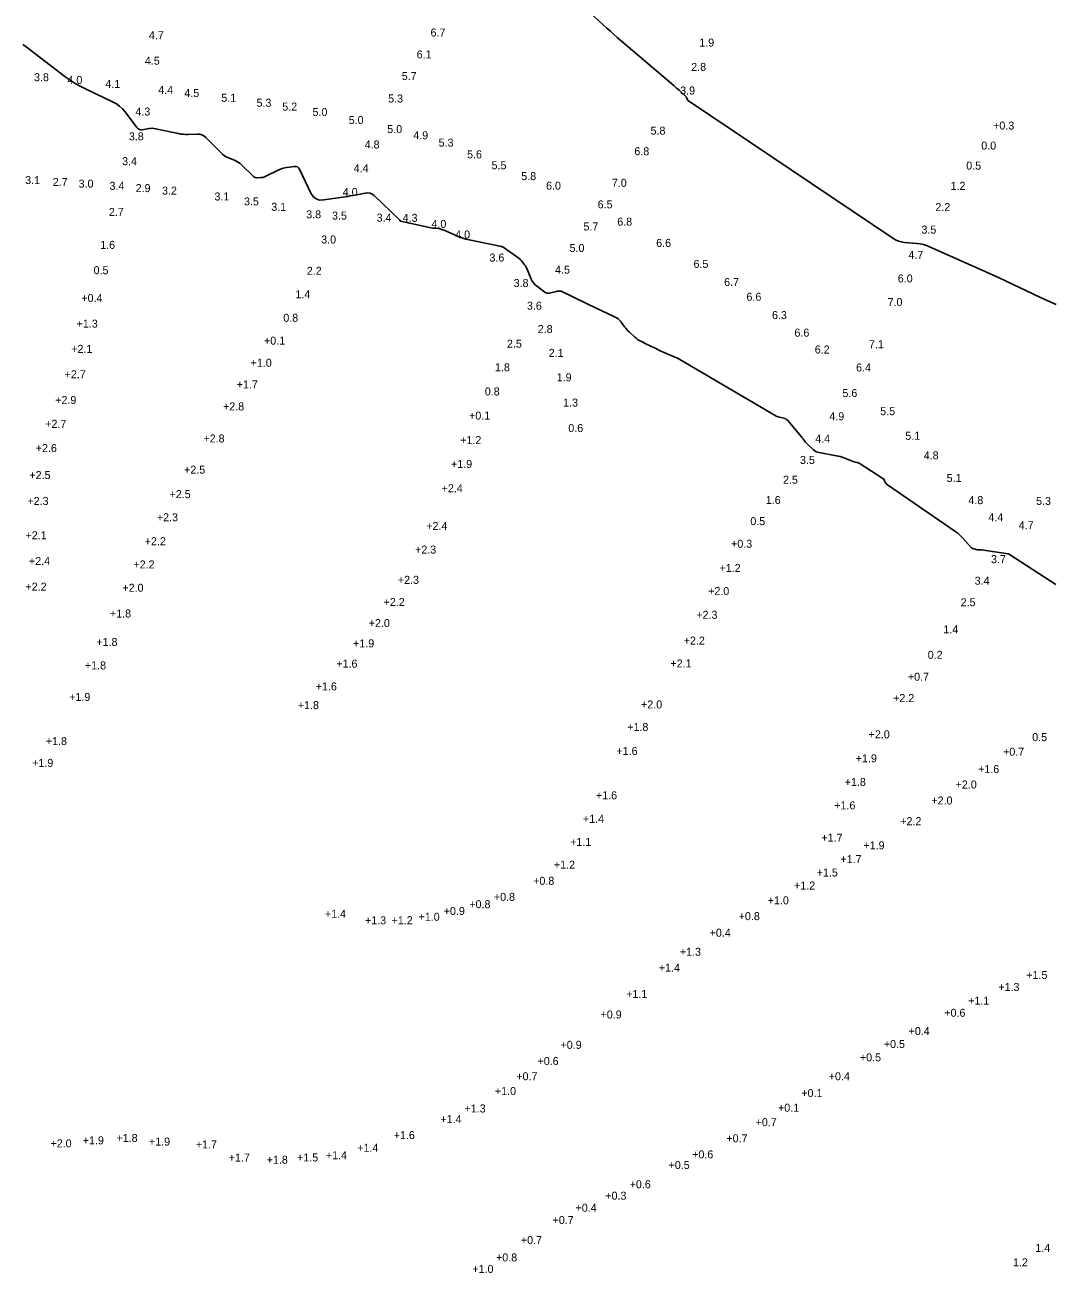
# Model space of a CAD drawing. Extents: x 837127 to 848654, y 3074248 to 3079868.
# Drawn here: x 845153 to 845553.7, y 3078633 to 3079120.3 of the extents above; entities that cross this region are included whole.
import ezdxf

# ---------------------------------------------------------------- set-up
doc = ezdxf.new("R2010")
doc.units = 0
for name, color, linetype in [('V-HYDS-MAJR', 7, 'Continuous'), ('V-HYDS-SOUN', 7, 'Continuous'), ('V-HYDS-SOUN-EXSS', 7, 'Continuous')]:
    doc.layers.add(name, color=color, linetype=linetype)

msp = doc.modelspace()

# ---------------------------------------------------------------- linework, layer by layer
at = {"layer": 'V-HYDS-MAJR'}
for points in [[(845373.58, 3079125.23), (845378.97, 3079120.24), (845380.29, 3079119.03), (845381.62, 3079117.83), (845382.97, 3079116.65), (845384.32, 3079115.48), (845406.55, 3079096.49), (845407.03, 3079096.08), (845407.5, 3079095.67), (845407.96, 3079095.26), (845408.43, 3079094.84), (845410.85, 3079092.66), (845411.02, 3079092.49), (845411.17, 3079092.31), (845411.3, 3079092.11), (845411.41, 3079091.89), (845411.98, 3079090.65), (845412, 3079090.61), (845412.04, 3079090.58), (845412.08, 3079090.55), (845412.12, 3079090.54), (845412.33, 3079090.51), (845412.38, 3079090.49), (845412.43, 3079090.48), (845412.48, 3079090.46), (845412.52, 3079090.43), (845491.95, 3079037.05), (845493.01, 3079036.42), (845494.12, 3079035.95), (845495.28, 3079035.62), (845496.49, 3079035.43), (845501.45, 3079034.97), (845502.67, 3079034.8), (845503.87, 3079034.54), (845505.05, 3079034.18), (845506.2, 3079033.73), (845523.53, 3079026.06), (845526.78, 3079024.61), (845530.01, 3079023.15), (845533.24, 3079021.66), (845536.45, 3079020.16), (845549.3, 3079014.1), (845552.52, 3079012.6), (845555.76, 3079011.15)], [(845555.56, 3078901.82), (845537.47, 3078913.53), (845536.97, 3078913.86), (845526.51, 3078915.43), (845526.15, 3078915.36), (845525.78, 3078915.34), (845525.42, 3078915.36), (845525.05, 3078915.42), (845523.59, 3078915.76), (845523.23, 3078915.87), (845522.91, 3078916.02), (845522.62, 3078916.23), (845522.35, 3078916.49), (845519.23, 3078919.99), (845518.61, 3078920.65), (845517.95, 3078921.27), (845517.26, 3078921.84), (845516.53, 3078922.38), (845489.88, 3078940.76), (845489.34, 3078941.21), (845488.93, 3078941.75), (845488.63, 3078942.36), (845488.47, 3078943.04), (845478.74, 3078949.29), (845477.98, 3078949.47), (845477.23, 3078949.67), (845476.48, 3078949.91), (845475.75, 3078950.18), (845472.84, 3078951.31), (845472.1, 3078951.57), (845471.36, 3078951.8), (845470.6, 3078951.99), (845469.84, 3078952.15), (845463.15, 3078953.34), (845462.56, 3078953.49), (845462, 3078953.71), (845461.49, 3078954.02), (845461.01, 3078954.4), (845458.75, 3078956.5), (845458.52, 3078956.73), (845458.29, 3078956.96), (845458.07, 3078957.21), (845457.87, 3078957.47), (845457.07, 3078958.51), (845456.87, 3078958.77), (845456.66, 3078959.02), (845456.45, 3078959.28), (845456.24, 3078959.53), (845450.87, 3078965.89), (845450.56, 3078966.2), (845450.21, 3078966.45), (845449.83, 3078966.64), (845449.41, 3078966.76), (845447.65, 3078967.15), (845447.21, 3078967.26), (845446.79, 3078967.4), (845446.38, 3078967.58), (845445.99, 3078967.79), (845408.71, 3078989.75), (845408.13, 3078990.07), (845407.54, 3078990.38), (845406.93, 3078990.65), (845406.32, 3078990.91), (845403.83, 3078991.88), (845403.21, 3078992.13), (845402.6, 3078992.4), (845401.99, 3078992.67), (845401.39, 3078992.96), (845398.81, 3078994.23), (845398.18, 3078994.54), (845397.55, 3078994.84), (845396.92, 3078995.15), (845396.29, 3078995.46), (845393.5, 3078996.82), (845392.87, 3078997.16), (845392.27, 3078997.54), (845391.7, 3078997.97), (845391.16, 3078998.44), (845388.99, 3079000.46), (845388.51, 3079000.94), (845388.04, 3079001.43), (845387.6, 3079001.94), (845387.19, 3079002.47), (845385.55, 3079004.63), (845385.12, 3079005.14), (845384.63, 3079005.58), (845384.1, 3079005.97), (845383.51, 3079006.28), (845379.7, 3079008.06), (845378.87, 3079008.45), (845378.03, 3079008.85), (845377.2, 3079009.25), (845376.36, 3079009.65), (845362.72, 3079016.29), (845362.56, 3079016.36), (845362.4, 3079016.41), (845362.23, 3079016.43), (845362.05, 3079016.43), (845361.35, 3079016.41), (845361.17, 3079016.4), (845361, 3079016.38), (845360.82, 3079016.35), (845360.65, 3079016.31), (845357.9, 3079015.65), (845357.4, 3079015.58), (845356.92, 3079015.62), (845356.46, 3079015.78), (845356.03, 3079016.04), (845352.78, 3079018.48), (845352.14, 3079019.03), (845351.59, 3079019.64), (845351.13, 3079020.33), (845350.75, 3079021.08), (845349.13, 3079024.92), (845348.92, 3079025.37), (845348.68, 3079025.81), (845348.42, 3079026.23), (845348.12, 3079026.63), (845346.89, 3079028.22), (845346.57, 3079028.6), (845346.22, 3079028.95), (845345.85, 3079029.28), (845345.45, 3079029.58), (845341.39, 3079032.36), (845341.21, 3079032.49), (845341.03, 3079032.62), (845340.85, 3079032.76), (845340.67, 3079032.89), (845339.96, 3079033.44), (845339.77, 3079033.57), (845339.58, 3079033.67), (845339.37, 3079033.75), (845339.16, 3079033.81), (845326.44, 3079036.44), (845325.21, 3079036.73), (845324, 3079037.08), (845322.81, 3079037.5), (845321.64, 3079037.98), (845317.01, 3079040.04), (845315.84, 3079040.49), (845314.64, 3079040.79), (845313.41, 3079040.96), (845312.16, 3079040.98), (845299.65, 3079043.76), (845299.4, 3079044.08), (845289.33, 3079053.7), (845288.57, 3079054.28), (845287.76, 3079054.64), (845286.87, 3079054.78), (845285.93, 3079054.69), (845282.01, 3079053.92), (845281.03, 3079053.74), (845280.05, 3079053.56), (845279.06, 3079053.4), (845278.08, 3079053.25), (845269.66, 3079051.99), (845268.05, 3079051.96), (845266.68, 3079052.4), (845265.56, 3079053.29), (845264.68, 3079054.64), (845260.22, 3079063.96), (845259.85, 3079064.52), (845259.38, 3079064.9), (845258.81, 3079065.09), (845258.14, 3079065.08), (845255.24, 3079064.7), (845254.52, 3079064.58), (845253.82, 3079064.4), (845253.14, 3079064.17), (845252.47, 3079063.88), (845246.58, 3079061.08), (845246.23, 3079060.93), (845245.88, 3079060.82), (845245.51, 3079060.75), (845245.14, 3079060.71), (845243.62, 3079060.61), (845243.25, 3079060.63), (845242.91, 3079060.71), (845242.6, 3079060.87), (845242.31, 3079061.1), (845237.58, 3079065.69), (845237.01, 3079066.19), (845236.4, 3079066.63), (845235.75, 3079067.02), (845235.07, 3079067.35), (845232.25, 3079068.53), (845231.56, 3079068.86), (845230.92, 3079069.25), (845230.32, 3079069.7), (845229.76, 3079070.21), (845223.59, 3079076.42), (845222.9, 3079077), (845222.14, 3079077.4), (845221.31, 3079077.63), (845220.41, 3079077.69), (845216.69, 3079077.58), (845215.76, 3079077.58), (845214.84, 3079077.63), (845213.92, 3079077.74), (845213.01, 3079077.91), (845204, 3079079.82), (845203.36, 3079079.92), (845202.72, 3079079.96), (845202.07, 3079079.94), (845201.43, 3079079.85), (845198.84, 3079079.37), (845198.22, 3079079.34), (845197.67, 3079079.46), (845197.18, 3079079.74), (845196.76, 3079080.19), (845192.04, 3079086.47), (845191.07, 3079087.63), (845189.98, 3079088.64), (845188.77, 3079089.5), (845187.45, 3079090.23), (845176.95, 3079095.19), (845174.77, 3079096.29), (845172.66, 3079097.5), (845170.61, 3079098.81), (845168.63, 3079100.23), (845153.47, 3079111.72), (845152.14, 3079112.74)]]:
    msp.add_lwpolyline(points, dxfattribs=at)

# ---------------------------------------------------------------- texts
at = {"layer": 'V-HYDS-SOUN'}
for s, p in [('4.7', (845201.41, 3079114.76)), ('6.7', (845311.39, 3079115.8)), ('1.9', (845416.34, 3079111.87)), ('4.5', (845199.83, 3079104.81)), ('6.1', (845305.99, 3079107.24)), ('5.7', (845300.16, 3079098.82)), ('2.8', (845413.2, 3079102.37)), ('3.8', (845156.55, 3079098.35)), ('4.0', (845169.6, 3079097.28)), ('4.1', (845184.42, 3079095.75)), ('4.4', (845205.05, 3079093.42)), ('4.5', (845215.24, 3079092.17)), ('5.1', (845229.68, 3079090.32)), ('5.3', (845294.84, 3079090.04)), ('3.9', (845408.88, 3079093.16)), ('4.3', (845196.14, 3079084.95)), ('5.3', (845243.44, 3079088.38)), ('5.2', (845253.5, 3079086.87)), ('5.0', (845265.29, 3079084.76)), ('5.0', (845279.44, 3079081.62)), ('+0.3 ', (845531.1, 3079079.47)), ('3.8', (845193.59, 3079075.26)), ('5.0', (845294.51, 3079078.1)), ('4.9', (845304.66, 3079075.67)), ('5.8', (845397.32, 3079077.49)), ('4.8', (845285.67, 3079072.08)), ('5.3', (845314.56, 3079072.82)), ('6.8', (845391, 3079069.45)), (' 0.0', (845525.31, 3079071.65)), ('3.4', (845190.94, 3079065.57)), ('5.6', (845325.67, 3079068.24)), ('4.4', (845281.37, 3079062.79)), ('5.5', (845335.23, 3079063.97)), ('5.8', (845346.83, 3079059.72)), ('0.5', (845520.62, 3079063.84)), ('3.1', (845153.08, 3079058.2)), ('2.7', (845163.87, 3079057.45)), ('3.0', (845173.96, 3079056.8)), ('3.4', (845186.03, 3079055.95)), ('2.9', (845196.24, 3079055.06)), ('6.0', (845356.51, 3079056.01)), ('1.2', (845514.5, 3079055.94)), ('3.2', (845206.53, 3079054.08)), ('3.1', (845227, 3079051.78)), ('3.5', (845238.56, 3079049.87)), ('4.0', (845277.12, 3079053.54)), ('2.7', (845185.78, 3079045.74)), ('3.1', (845249.19, 3079047.74)), ('3.8', (845262.85, 3079044.82)), ('2.2', (845508.56, 3079047.65)), ('3.5', (845272.92, 3079044.33)), ('3.4', (845290.33, 3079043.51)), ('4.3', (845300.51, 3079043.44)), ('4.0', (845311.76, 3079041.07)), ('5.7', (845371.11, 3079040.08)), ('6.8', (845384.32, 3079041.97)), ('4.0', (845321.03, 3079036.95)), ('3.5', (845503.11, 3079038.86)), ('1.6', (845182.39, 3079032.89)), ('3.0', (845268.69, 3079034.99)), ('5.0', (845365.68, 3079031.68)), ('6.6', (845399.52, 3079033.66)), ('3.6', (845334.41, 3079027.94)), ('6.5', (845414.1, 3079025.45)), ('4.7', (845498, 3079028.96)), ('0.5', (845179.8, 3079023)), ('2.2', (845263.06, 3079022.76)), ('4.5', (845360.04, 3079023.22)), ('3.8', (845343.85, 3079018.02)), ('6.7', (845426.06, 3079018.37)), ('6.0', (845493.87, 3079019.79)), ('+0.4 ', (845175.02, 3079012.15)), ('1.4', (845258.64, 3079013.62)), ('6.6', (845434.78, 3079012.64)), ('3.6', (845349.05, 3079009.15)), ('7.0', (845489.9, 3079010.55)), ('+1.3 ', (845173.17, 3079002.14)), ('0.8', (845253.9, 3079004.42)), ('6.3', (845444.75, 3079005.48)), ('2.8', (845353.26, 3079000.02)), ('6.6', (845453.52, 3078998.62)), ('+2.1 ', (845171.08, 3078992.29)), ('+0.1 ', (845246.37, 3078995.5)), ('2.5', (845341.22, 3078994.31)), ('6.2', (845461.45, 3078992.04)), ('7.1', (845482.61, 3078994.12)), ('+1.0 ', (845241.14, 3078986.87)), ('2.1', (845357.55, 3078990.71)), ('+2.7 ', (845168.5, 3078982.37)), ('1.8', (845336.57, 3078985.1)), ('6.4', (845477.58, 3078985.03)), ('+1.7 ', (845235.71, 3078978.41)), ('1.9', (845360.66, 3078981.18)), ('+2.9 ', (845164.81, 3078972.31)), ('0.8', (845332.59, 3078975.66)), ('5.6', (845472.25, 3078975.02)), ('+2.8 ', (845230.35, 3078969.83)), ('1.3', (845363.18, 3078971.32)), ('5.5', (845487.02, 3078967.96)), ('+2.7 ', (845160.91, 3078963.02)), ('+0.1 ', (845326.45, 3078966.24)), ('4.9', (845467.15, 3078965.98)), ('+2.8 ', (845222.71, 3078957.3)), ('4.4', (845461.64, 3078957.26)), ('5.1', (845496.82, 3078958.35)), ('+2.6 ', (845157.22, 3078953.56)), ('+1.2 ', (845322.97, 3078956.68)), ('+1.9 ', (845319.39, 3078947.34)), ('3.5', (845455.67, 3078948.93)), ('4.8', (845504.01, 3078950.7)), ('+2.5 ', (845154.72, 3078943.03)), ('+2.5 ', (845215.15, 3078945.14)), ('+2.4 ', (845315.73, 3078937.87)), ('2.5', (845449.04, 3078941.2)), ('5.1', (845512.95, 3078941.88)), ('+2.3 ', (845153.97, 3078932.92)), ('+2.5 ', (845209.47, 3078935.57)), ('1.6', (845442.33, 3078933.29)), ('4.8', (845521.46, 3078933.23)), ('5.3', (845547.88, 3078932.92)), ('+2.3 ', (845204.53, 3078926.54)), ('+2.4 ', (845309.73, 3078923.18)), ('0.5', (845436.3, 3078925.03)), ('4.4', (845529.27, 3078926.58)), ('4.7', (845541.12, 3078923.45)), ('+2.1 ', (845153.22, 3078919.52)), ('+2.2 ', (845199.78, 3078917.2)), ('+2.3 ', (845305.35, 3078913.93)), ('+0.3 ', (845428.77, 3078916.2)), ('+2.4 ', (845154.57, 3078909.49)), ('3.7', (845530.28, 3078910.2)), ('+2.2 ', (845195.37, 3078908.12)), ('+1.2 ', (845424.25, 3078906.78)), ('+2.2 ', (845153.19, 3078899.46)), ('+2.0 ', (845191.05, 3078899.02)), ('+2.3 ', (845298.64, 3078902.11)), ('3.4', (845523.89, 3078901.77)), ('+2.0 ', (845419.8, 3078897.72)), ('+1.8 ', (845186.2, 3078888.97)), ('+2.2 ', (845293.07, 3078893.47)), ('2.5', (845518.41, 3078893.35)), ('+2.0 ', (845287.26, 3078885.24)), ('+2.3 ', (845415.19, 3078888.47)), ('1.4', (845511.66, 3078882.79)), ('+1.8 ', (845180.89, 3078877.88)), ('+1.9 ', (845281.15, 3078877.31)), ('+2.2 ', (845410.28, 3078878.4)), ('+1.6 ', (845274.6, 3078869.4)), ('+2.1 ', (845405.08, 3078869.48)), ('0.2', (845505.57, 3078872.85)), ('+1.8 ', (845176.42, 3078868.71)), ('+1.6 ', (845266.57, 3078860.52)), ('+0.7 ', (845497.81, 3078864.28)), ('+1.9 ', (845170.28, 3078856.41)), ('+2.2 ', (845492.05, 3078855.95)), ('+1.8 ', (845259.56, 3078853.2)), ('+2.0 ', (845393.61, 3078853.48)), ('+1.8 ', (845388.21, 3078844.68)), ('+2.0 ', (845482.49, 3078841.81)), ('0.5', (845546.37, 3078840.71)), ('+1.8 ', (845161.16, 3078839.17)), ('+1.6 ', (845383.99, 3078835.32)), ('+1.9 ', (845155.8, 3078830.67)), ('+1.9 ', (845477.46, 3078832.42)), ('+0.7 ', (845535, 3078835.02)), ('+1.6 ', (845525.24, 3078828.23)), ('+1.8 ', (845473.14, 3078823.2)), ('+2.0 ', (845516.46, 3078822.21)), ('+1.6 ', (845376.01, 3078817.99)), ('+2.0 ', (845506.98, 3078815.98)), ('+1.6 ', (845469.07, 3078814.06)), ('+1.4 ', (845370.92, 3078808.81)), ('+2.2 ', (845494.83, 3078807.9)), ('+1.7 ', (845464.04, 3078801.47)), ('+1.1 ', (845365.9, 3078799.81)), ('+1.9 ', (845480.46, 3078798.46)), ('+1.7 ', (845471.47, 3078793.09)), ('+1.2 ', (845359.59, 3078790.93)), ('+1.5 ', (845462.2, 3078787.85)), ('+0.8 ', (845351.48, 3078784.61)), ('+1.2 ', (845453.37, 3078782.78)), ('+0.8 ', (845336.13, 3078778.35)), ('+1.0 ', (845443.09, 3078776.98)), ('+0.9 ', (845316.54, 3078772.84)), ('+0.8 ', (845326.54, 3078775.48)), ('+1.4 ', (845270.14, 3078771.74)), ('+1.3 ', (845285.81, 3078769.18)), ('+1.2 ', (845296.19, 3078769.24)), ('+1.0 ', (845306.72, 3078770.58)), ('+0.8 ', (845431.74, 3078770.83)), ('+0.4 ', (845420.4, 3078764.35)), ('+1.3 ', (845408.76, 3078756.91)), ('+1.4 ', (845400.57, 3078750.71)), ('+1.5 ', (845544.05, 3078747.85)), ('+1.3 ', (845533.15, 3078743.16)), ('+1.1 ', (845387.8, 3078740.45)), ('+1.1 ', (845521.36, 3078737.83)), ('+0.6 ', (845512.04, 3078733.1)), ('+0.9 ', (845377.78, 3078732.42)), ('+0.4 ', (845498.1, 3078725.96)), ('+0.9 ', (845362.15, 3078720.58)), ('+0.5 ', (845488.42, 3078720.9)), ('+0.6 ', (845353.17, 3078714.25)), ('+0.5 ', (845479.08, 3078715.7)), ('+0.7 ', (845344.9, 3078708.31)), ('+0.4 ', (845466.91, 3078708.31)), ('+1.0 ', (845336.53, 3078702.53)), ('+0.1 ', (845456.21, 3078701.75)), ('+1.3 ', (845324.67, 3078695.73)), ('+0.1 ', (845447.11, 3078696.02)), ('+1.4 ', (845315.23, 3078691.57)), ('+0.7 ', (845438.35, 3078690.38)), ('+1.8 ', (845188.75, 3078684.24)), ('+1.6 ', (845297.01, 3078685.33)), ('+2.0 ', (845162.97, 3078682.1)), ('+1.9 ', (845175.56, 3078683.28)), ('+1.9 ', (845201.43, 3078682.8)), ('+1.7 ', (845219.73, 3078681.68)), ('+1.4 ', (845282.78, 3078680.37)), ('+0.7 ', (845426.94, 3078684.08)), ('+1.7 ', (845232.56, 3078676.55)), ('+1.8 ', (845247.4, 3078675.72)), ('+1.5 ', (845259.27, 3078676.61)), ('+1.4 ', (845270.53, 3078677.48)), ('+0.6 ', (845413.57, 3078677.8)), ('+0.5 ', (845404.36, 3078673.65)), ('+0.6 ', (845389.16, 3078666.15)), ('+0.3 ', (845379.65, 3078661.68)), ('+0.4 ', (845368.01, 3078656.99)), ('+0.7 ', (845359.05, 3078652.19)), ('+0.7 ', (845346.67, 3078644.35)), ('1.4', (845547.58, 3078641.28)), ('+0.8 ', (845336.98, 3078637.58)), ('1.2', (845538.85, 3078635.65)), ('+1.0 ', (845327.73, 3078633.09))]:
    msp.add_text(s, height=3.125, dxfattribs=at).set_placement(p)
at = {"layer": 'V-HYDS-SOUN-EXSS'}
for s, p in [('7.0', (845382.22, 3079057.12)), ('6.5', (845376.67, 3079048.7)), ('0.6', (845365.2, 3078961.37))]:
    msp.add_text(s, height=3.125, dxfattribs=at).set_placement(p)

doc.saveas('drawing.dxf')
